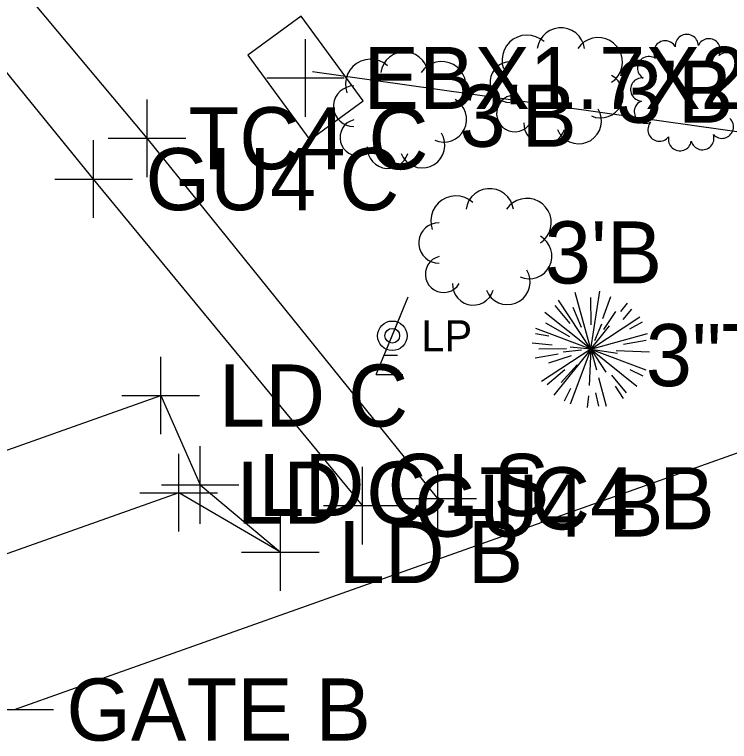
# Model space of a CAD drawing. Extents: x 1363693 to 1365209, y 422201 to 424153.
# Drawn here: x 1363860.29 to 1363878.71, y 423091.66 to 423110.38 of the extents above; entities that cross this region are included whole.
import ezdxf

# ---------------------------------------------------------------- set-up
doc = ezdxf.new("R2010")
doc.units = 0
for name, color, linetype in [('BASELINE-CL-RW', 7, 'Continuous'), ('PV_X_Driveway', 7, 'Continuous'), ('RD_X_Fence', 7, 'Continuous'), ('RD_X_Misc_Items', 7, 'Continuous'), ('RD_X_Text', 7, 'Continuous'), ('SG_X_Wiring', 7, 'Continuous'), ('SV_X_Original_Ground', 7, 'Continuous'), ('SV_X_Shot_Marker', 7, 'Continuous'), ('UT_X_Electric', 7, 'Continuous'), ('UT_X_Electric_Cells', 7, 'Continuous'), ('VG_X_Cells', 7, 'Continuous'), ('VG_X_Text', 7, 'Continuous')]:
    doc.layers.add(name, color=color, linetype=linetype)

msp = doc.modelspace()

# ---------------------------------------------------------------- linework, layer by layer
at = {"layer": 'BASELINE-CL-RW'}
msp.add_lwpolyline([(1363871.193, 423097.923), (1363863.7, 423107.198), (1363855.331, 423117.197), (1363852.206, 423120.83)], dxfattribs=at)
at = {"layer": 'PV_X_Driveway'}
msp.add_lwpolyline([(1363869.251, 423097.736), (1363862.325, 423106.145), (1363854.135, 423116.203), (1363852, 423118.789), (1363852.206, 423120.83)], dxfattribs=at)
at = {"layer": 'RD_X_Fence'}
msp.add_line((1363860.286, 423092.484), (1363885.607, 423101.471), dxfattribs=at)
at = {"layer": 'RD_X_Misc_Items'}
for p, q in [((1363869.608, 423101.11), (1363870.434, 423103.11)), ((1363869.815, 423101.61), (1363870.227, 423102.61)), ((1363869.815, 423101.61), (1363870.155, 423101.61)), ((1363869.608, 423101.11), (1363870.289, 423101.11))]:
    msp.add_line(p, q, dxfattribs=at)
for radius in [0.38, 0.19]:
    msp.add_circle((1363870.021, 423102.11), radius, dxfattribs=at)
at = {"layer": 'SG_X_Wiring'}
for p, q in [((1363850.877, 423095.89), (1363864.054, 423100.572)), ((1363864.054, 423100.572), (1363865.07, 423098.269)), ((1363865.07, 423098.269), (1363867.138, 423096.54)), ((1363864.519, 423098.068), (1363851.566, 423093.462)), ((1363867.138, 423096.54), (1363864.519, 423098.068))]:
    msp.add_line(p, q, dxfattribs=at)
at = {"layer": 'SV_X_Original_Ground'}
msp.add_line((1363859.286, 423092.484), (1363861.286, 423092.484), dxfattribs=at)
at = {"layer": 'SV_X_Shot_Marker'}
for p, q in [((1363867.784, 423107.75), (1363867.784, 423109.75)), ((1363866.784, 423108.75), (1363868.784, 423108.75)), ((1363863.7, 423106.198), (1363863.7, 423108.198)), ((1363862.325, 423105.145), (1363862.325, 423107.145)), ((1363862.7, 423107.198), (1363864.7, 423107.198)), ((1363861.325, 423106.145), (1363863.325, 423106.145)), ((1363864.054, 423099.572), (1363864.054, 423101.572)), ((1363863.054, 423100.572), (1363865.054, 423100.572)), ((1363865.07, 423097.269), (1363865.07, 423099.269)), ((1363864.519, 423097.068), (1363864.519, 423099.068)), ((1363871.193, 423096.923), (1363871.193, 423098.923)), ((1363869.251, 423096.736), (1363869.251, 423098.736)), ((1363864.07, 423098.269), (1363866.07, 423098.269)), ((1363863.519, 423098.068), (1363865.519, 423098.068)), ((1363870.193, 423097.923), (1363872.193, 423097.923)), ((1363868.251, 423097.736), (1363870.251, 423097.736)), ((1363867.138, 423095.54), (1363867.138, 423097.54)), ((1363866.138, 423096.54), (1363868.138, 423096.54))]:
    msp.add_line(p, q, dxfattribs=at)
at = {"layer": 'UT_X_Electric'}
msp.add_lwpolyline([(1363867.968, 423108.916), (1363973.038, 423094.077), (1364006.657, 423093.464)], dxfattribs=at)
at = {"layer": 'UT_X_Electric_Cells'}
msp.add_lwpolyline([(1363867.896, 423107.159), (1363869.268, 423108.164), (1363867.672, 423110.341), (1363866.3, 423109.336)], close=True, dxfattribs=at)
msp.add_lwpolyline([(1363867.896, 423107.159), (1363869.268, 423108.164), (1363867.672, 423110.341), (1363866.3, 423109.336)], close=True, dxfattribs=at)
at = {"layer": 'VG_X_Cells'}
for p, q in [((1363875.136, 423101.764), (1363874.735, 423103.227)), ((1363875.136, 423101.764), (1363875.367, 423103.263)), ((1363875.445, 423102.559), (1363875.651, 423103.119)), ((1363875.445, 423102.559), (1363875.651, 423103.119)), ((1363875.136, 423101.764), (1363874.303, 423103.031)), ((1363875.145, 423102.389), (1363875.139, 423103.1)), ((1363875.914, 423102.736), (1363876.084, 423102.948)), ((1363874.602, 423102.429), (1363874.22, 423102.887)), ((1363874.898, 423102.323), (1363874.679, 423102.839)), ((1363875.473, 423102.27), (1363875.784, 423102.736)), ((1363875.969, 423102.533), (1363876.195, 423102.798)), ((1363875.136, 423101.764), (1363873.952, 423102.712)), ((1363875.136, 423101.764), (1363876.403, 423102.597)), ((1363874.599, 423102.085), (1363873.981, 423102.434)), ((1363875.136, 423101.764), (1363875.617, 423102.365)), ((1363875.237, 423101.986), (1363875.425, 423102.414)), ((1363876.144, 423102.289), (1363876.467, 423102.468)), ((1363875.136, 423101.764), (1363873.717, 423102.299)), ((1363875.136, 423101.764), (1363876.599, 423102.165)), ((1363874.054, 423102.101), (1363873.712, 423102.164)), ((1363875.979, 423101.894), (1363876.567, 423101.996)), ((1363874.145, 423101.868), (1363873.628, 423101.923)), ((1363875.136, 423101.764), (1363874.607, 423101.82)), ((1363874.293, 423101.634), (1363873.705, 423101.532)), ((1363874.511, 423101.773), (1363873.8, 423101.767)), ((1363875.136, 423101.764), (1363873.869, 423100.931)), ((1363875.136, 423101.764), (1363874.188, 423100.58)), ((1363874.893, 423101.74), (1363874.428, 423101.689)), ((1363875.136, 423101.764), (1363874.601, 423100.345)), ((1363875.136, 423101.764), (1363875.092, 423100.832)), ((1363875.136, 423101.764), (1363875.283, 423101.229)), ((1363875.136, 423101.764), (1363875.524, 423101.175)), ((1363875.136, 423101.764), (1363876.32, 423100.816)), ((1363875.136, 423101.764), (1363876.555, 423101.229)), ((1363875.136, 423101.764), (1363875.822, 423101.66)), ((1363875.791, 423101.733), (1363876.651, 423101.693)), ((1363874.63, 423101.596), (1363874.049, 423101.403)), ((1363874.471, 423101.23), (1363874.013, 423100.848)), ((1363874.782, 423101.365), (1363874.375, 423100.908)), ((1363876.146, 423101.243), (1363876.478, 423101.082)), ((1363875.67, 423101.099), (1363876.052, 423100.641)), ((1363875.336, 423101.033), (1363875.537, 423100.301)), ((1363874.615, 423100.754), (1363874.454, 423100.422)), ((1363875.762, 423100.813), (1363875.969, 423100.497)), ((1363875.077, 423100.562), (1363875.044, 423100.263)), ((1363875.257, 423100.637), (1363875.334, 423100.298))]:
    msp.add_line(p, q, dxfattribs=at)
for points in [[(1363874.977, 423109.512), (1363874.95, 423109.626), (1363874.901, 423109.733), (1363874.833, 423109.828), (1363874.749, 423109.909), (1363874.65, 423109.972), (1363874.541, 423110.016), (1363874.426, 423110.038), (1363874.309, 423110.038), (1363874.194, 423110.016), (1363874.085, 423109.972), (1363873.987, 423109.909), (1363873.902, 423109.828), (1363873.834, 423109.733), (1363873.786, 423109.626), (1363873.758, 423109.512)], [(1363873.932, 423109.686), (1363873.834, 423109.76), (1363873.724, 423109.814), (1363873.606, 423109.846), (1363873.484, 423109.855), (1363873.362, 423109.841), (1363873.246, 423109.804), (1363873.138, 423109.746), (1363873.043, 423109.669), (1363872.964, 423109.575), (1363872.904, 423109.468), (1363872.866, 423109.352), (1363872.85, 423109.231), (1363872.857, 423109.108), (1363872.887, 423108.99)], [(1363875.674, 423108.642), (1363875.765, 423108.715), (1363875.84, 423108.804), (1363875.898, 423108.905), (1363875.936, 423109.016), (1363875.953, 423109.131), (1363875.948, 423109.248), (1363875.922, 423109.362), (1363875.875, 423109.468), (1363875.809, 423109.565), (1363875.726, 423109.647), (1363875.63, 423109.713), (1363875.523, 423109.76), (1363875.409, 423109.786), (1363875.293, 423109.791), (1363875.177, 423109.774), (1363875.067, 423109.736), (1363874.966, 423109.678), (1363874.877, 423109.603), (1363874.803, 423109.512)], [(1363870.942, 423108.892), (1363870.915, 423109.006), (1363870.866, 423109.113), (1363870.798, 423109.208), (1363870.714, 423109.289), (1363870.615, 423109.352), (1363870.506, 423109.396), (1363870.391, 423109.418), (1363870.274, 423109.418), (1363870.159, 423109.396), (1363870.05, 423109.352), (1363869.952, 423109.289), (1363869.867, 423109.208), (1363869.799, 423109.113), (1363869.751, 423109.006), (1363869.723, 423108.892)], [(1363869.897, 423109.066), (1363869.799, 423109.14), (1363869.689, 423109.194), (1363869.571, 423109.226), (1363869.449, 423109.235), (1363869.327, 423109.221), (1363869.211, 423109.184), (1363869.103, 423109.126), (1363869.008, 423109.049), (1363868.929, 423108.955), (1363868.869, 423108.848), (1363868.831, 423108.732), (1363868.815, 423108.611), (1363868.822, 423108.488), (1363868.852, 423108.37)], [(1363871.639, 423108.022), (1363871.73, 423108.095), (1363871.805, 423108.184), (1363871.863, 423108.285), (1363871.901, 423108.396), (1363871.918, 423108.511), (1363871.913, 423108.628), (1363871.887, 423108.742), (1363871.84, 423108.848), (1363871.774, 423108.945), (1363871.691, 423109.027), (1363871.595, 423109.093), (1363871.488, 423109.14), (1363871.374, 423109.166), (1363871.258, 423109.171), (1363871.142, 423109.154), (1363871.032, 423109.116), (1363870.931, 423109.058), (1363870.842, 423108.983), (1363870.768, 423108.892)], [(1363873.062, 423109.164), (1363872.965, 423109.155), (1363872.873, 423109.129), (1363872.786, 423109.086), (1363872.71, 423109.028), (1363872.645, 423108.956), (1363872.594, 423108.874), (1363872.559, 423108.784), (1363872.541, 423108.69), (1363872.541, 423108.593), (1363872.559, 423108.499), (1363872.594, 423108.409), (1363872.645, 423108.327), (1363872.71, 423108.255), (1363872.786, 423108.197), (1363872.873, 423108.154), (1363872.965, 423108.128), (1363873.062, 423108.119)], [(1363875.151, 423107.771), (1363875.257, 423107.736), (1363875.367, 423107.721), (1363875.478, 423107.728), (1363875.586, 423107.755), (1363875.686, 423107.803), (1363875.776, 423107.868), (1363875.852, 423107.95), (1363875.911, 423108.044), (1363875.951, 423108.148), (1363875.971, 423108.257), (1363875.969, 423108.368), (1363875.947, 423108.477), (1363875.904, 423108.58), (1363875.843, 423108.673), (1363875.765, 423108.752), (1363875.674, 423108.816)], [(1363869.027, 423108.544), (1363868.93, 423108.535), (1363868.838, 423108.509), (1363868.751, 423108.466), (1363868.675, 423108.408), (1363868.61, 423108.336), (1363868.559, 423108.254), (1363868.524, 423108.164), (1363868.506, 423108.07), (1363868.506, 423107.973), (1363868.524, 423107.879), (1363868.559, 423107.789), (1363868.61, 423107.707), (1363868.675, 423107.635), (1363868.751, 423107.577), (1363868.838, 423107.534), (1363868.93, 423107.508), (1363869.027, 423107.499)], [(1363871.116, 423107.151), (1363871.222, 423107.116), (1363871.332, 423107.101), (1363871.443, 423107.108), (1363871.551, 423107.135), (1363871.651, 423107.183), (1363871.741, 423107.248), (1363871.817, 423107.33), (1363871.876, 423107.424), (1363871.916, 423107.528), (1363871.936, 423107.637), (1363871.934, 423107.748), (1363871.912, 423107.857), (1363871.869, 423107.96), (1363871.808, 423108.053), (1363871.73, 423108.132), (1363871.639, 423108.196)], [(1363873.062, 423108.293), (1363872.975, 423108.261), (1363872.896, 423108.214), (1363872.828, 423108.151), (1363872.774, 423108.077), (1363872.735, 423107.993), (1363872.713, 423107.904), (1363872.709, 423107.811), (1363872.723, 423107.72), (1363872.755, 423107.634), (1363872.803, 423107.555), (1363872.865, 423107.487), (1363872.939, 423107.432), (1363873.023, 423107.393), (1363873.112, 423107.371), (1363873.204, 423107.367), (1363873.296, 423107.381), (1363873.382, 423107.412), (1363873.461, 423107.46), (1363873.529, 423107.522), (1363873.584, 423107.597)], [(1363874.281, 423107.422), (1363874.333, 423107.321), (1363874.404, 423107.232), (1363874.491, 423107.158), (1363874.59, 423107.103), (1363874.698, 423107.068), (1363874.812, 423107.054), (1363874.925, 423107.063), (1363875.035, 423107.093), (1363875.137, 423107.144), (1363875.227, 423107.213), (1363875.302, 423107.299), (1363875.359, 423107.398), (1363875.395, 423107.506), (1363875.411, 423107.618), (1363875.404, 423107.732), (1363875.375, 423107.842), (1363875.326, 423107.945)], [(1363869.027, 423107.673), (1363868.94, 423107.641), (1363868.861, 423107.594), (1363868.793, 423107.531), (1363868.739, 423107.457), (1363868.7, 423107.373), (1363868.678, 423107.284), (1363868.674, 423107.191), (1363868.688, 423107.1), (1363868.72, 423107.014), (1363868.768, 423106.935), (1363868.83, 423106.867), (1363868.904, 423106.812), (1363868.988, 423106.773), (1363869.077, 423106.751), (1363869.169, 423106.747), (1363869.261, 423106.761), (1363869.347, 423106.792), (1363869.426, 423106.84), (1363869.494, 423106.902), (1363869.549, 423106.977)], [(1363873.41, 423107.597), (1363873.416, 423107.494), (1363873.441, 423107.394), (1363873.485, 423107.301), (1363873.546, 423107.219), (1363873.621, 423107.149), (1363873.709, 423107.095), (1363873.805, 423107.059), (1363873.907, 423107.042), (1363874.009, 423107.045), (1363874.11, 423107.068), (1363874.204, 423107.109), (1363874.288, 423107.167), (1363874.36, 423107.241), (1363874.416, 423107.327), (1363874.455, 423107.422)], [(1363870.246, 423106.802), (1363870.298, 423106.701), (1363870.369, 423106.612), (1363870.456, 423106.538), (1363870.555, 423106.483), (1363870.663, 423106.448), (1363870.777, 423106.434), (1363870.89, 423106.443), (1363871, 423106.473), (1363871.102, 423106.524), (1363871.192, 423106.593), (1363871.267, 423106.679), (1363871.324, 423106.778), (1363871.36, 423106.886), (1363871.376, 423106.998), (1363871.369, 423107.112), (1363871.34, 423107.222), (1363871.291, 423107.325)], [(1363869.375, 423106.977), (1363869.381, 423106.874), (1363869.406, 423106.774), (1363869.45, 423106.681), (1363869.511, 423106.599), (1363869.586, 423106.529), (1363869.674, 423106.475), (1363869.77, 423106.439), (1363869.872, 423106.422), (1363869.974, 423106.425), (1363870.075, 423106.448), (1363870.169, 423106.489), (1363870.253, 423106.547), (1363870.325, 423106.621), (1363870.381, 423106.707), (1363870.42, 423106.802)], [(1363873.141, 423105.371), (1363873.114, 423105.485), (1363873.065, 423105.592), (1363872.997, 423105.687), (1363872.913, 423105.768), (1363872.814, 423105.831), (1363872.705, 423105.875), (1363872.59, 423105.897), (1363872.473, 423105.897), (1363872.358, 423105.875), (1363872.249, 423105.831), (1363872.151, 423105.768), (1363872.066, 423105.687), (1363871.998, 423105.592), (1363871.95, 423105.485), (1363871.922, 423105.371)], [(1363872.096, 423105.545), (1363871.998, 423105.619), (1363871.888, 423105.673), (1363871.77, 423105.705), (1363871.648, 423105.714), (1363871.526, 423105.7), (1363871.41, 423105.663), (1363871.302, 423105.605), (1363871.207, 423105.528), (1363871.128, 423105.434), (1363871.068, 423105.327), (1363871.03, 423105.211), (1363871.014, 423105.09), (1363871.021, 423104.967), (1363871.051, 423104.849)], [(1363873.838, 423104.501), (1363873.929, 423104.574), (1363874.004, 423104.663), (1363874.062, 423104.764), (1363874.1, 423104.875), (1363874.117, 423104.99), (1363874.112, 423105.107), (1363874.086, 423105.221), (1363874.039, 423105.327), (1363873.973, 423105.424), (1363873.89, 423105.506), (1363873.794, 423105.572), (1363873.687, 423105.619), (1363873.573, 423105.645), (1363873.457, 423105.65), (1363873.341, 423105.633), (1363873.231, 423105.595), (1363873.13, 423105.537), (1363873.041, 423105.462), (1363872.967, 423105.371)], [(1363871.226, 423105.023), (1363871.129, 423105.014), (1363871.037, 423104.988), (1363870.95, 423104.945), (1363870.874, 423104.887), (1363870.809, 423104.815), (1363870.758, 423104.733), (1363870.723, 423104.643), (1363870.705, 423104.549), (1363870.705, 423104.452), (1363870.723, 423104.358), (1363870.758, 423104.268), (1363870.809, 423104.186), (1363870.874, 423104.114), (1363870.95, 423104.056), (1363871.037, 423104.013), (1363871.129, 423103.987), (1363871.226, 423103.978)], [(1363873.315, 423103.63), (1363873.421, 423103.595), (1363873.531, 423103.58), (1363873.642, 423103.587), (1363873.75, 423103.614), (1363873.85, 423103.662), (1363873.94, 423103.727), (1363874.016, 423103.809), (1363874.075, 423103.903), (1363874.115, 423104.007), (1363874.135, 423104.116), (1363874.133, 423104.227), (1363874.111, 423104.336), (1363874.068, 423104.439), (1363874.007, 423104.532), (1363873.929, 423104.611), (1363873.838, 423104.675)], [(1363871.226, 423104.152), (1363871.139, 423104.12), (1363871.06, 423104.073), (1363870.992, 423104.01), (1363870.938, 423103.936), (1363870.899, 423103.852), (1363870.877, 423103.763), (1363870.873, 423103.67), (1363870.887, 423103.579), (1363870.919, 423103.493), (1363870.967, 423103.414), (1363871.029, 423103.346), (1363871.103, 423103.291), (1363871.187, 423103.252), (1363871.276, 423103.23), (1363871.368, 423103.226), (1363871.46, 423103.24), (1363871.546, 423103.271), (1363871.625, 423103.319), (1363871.693, 423103.381), (1363871.748, 423103.456)], [(1363872.445, 423103.281), (1363872.497, 423103.18), (1363872.568, 423103.091), (1363872.655, 423103.017), (1363872.754, 423102.962), (1363872.862, 423102.927), (1363872.976, 423102.913), (1363873.089, 423102.922), (1363873.199, 423102.952), (1363873.301, 423103.003), (1363873.391, 423103.072), (1363873.466, 423103.158), (1363873.523, 423103.257), (1363873.559, 423103.365), (1363873.575, 423103.477), (1363873.568, 423103.591), (1363873.539, 423103.701), (1363873.49, 423103.804)], [(1363871.574, 423103.456), (1363871.58, 423103.353), (1363871.605, 423103.253), (1363871.649, 423103.16), (1363871.71, 423103.078), (1363871.785, 423103.008), (1363871.873, 423102.954), (1363871.969, 423102.918), (1363872.071, 423102.901), (1363872.173, 423102.904), (1363872.274, 423102.927), (1363872.368, 423102.968), (1363872.452, 423103.026), (1363872.524, 423103.1), (1363872.58, 423103.186), (1363872.619, 423103.281)]]:
    msp.add_lwpolyline(points, dxfattribs=at)
for points in [[(1363877.579, 423108.415), (1363877.668, 423108.363), (1363877.668, 423108.363), (1363877.565, 423108.363)], [(1363877.565, 423108.363), (1363877.668, 423108.363), (1363877.668, 423108.363), (1363877.579, 423108.311)], [(1363877.616, 423108.452), (1363877.668, 423108.363), (1363877.668, 423108.363), (1363877.579, 423108.415)], [(1363877.579, 423108.311), (1363877.668, 423108.363), (1363877.668, 423108.363), (1363877.616, 423108.274)], [(1363877.668, 423108.466), (1363877.668, 423108.363), (1363877.668, 423108.363), (1363877.616, 423108.452)], [(1363877.616, 423108.274), (1363877.668, 423108.363), (1363877.668, 423108.363), (1363877.668, 423108.26)], [(1363877.72, 423108.452), (1363877.668, 423108.363), (1363877.668, 423108.363), (1363877.668, 423108.466)], [(1363877.757, 423108.415), (1363877.668, 423108.363), (1363877.668, 423108.363), (1363877.72, 423108.452)], [(1363877.771, 423108.363), (1363877.668, 423108.363), (1363877.668, 423108.363), (1363877.757, 423108.415)], [(1363877.668, 423108.26), (1363877.668, 423108.363), (1363877.668, 423108.363), (1363877.72, 423108.274)], [(1363877.72, 423108.274), (1363877.668, 423108.363), (1363877.668, 423108.363), (1363877.757, 423108.311)], [(1363877.757, 423108.311), (1363877.668, 423108.363), (1363877.668, 423108.363), (1363877.771, 423108.363)]]:
    msp.add_lwpolyline(points, close=True, dxfattribs=at)
for centre, start, end in [((1363877.611, 423109.576), 1.241, 184.1237), ((1363877.054, 423109.411), 28.9333, 211.816), ((1363878.181, 423109.464), 333.5487, 156.4314), ((1363876.637, 423109.005), 56.6256, 239.5083), ((1363878.634, 423109.099), 305.8564, 128.7391), ((1363876.457, 423108.453), 84.3179, 267.2006), ((1363876.554, 423107.88), 112.0103, 294.8929), ((1363876.906, 423107.417), 139.7026, 322.5852), ((1363878.515, 423107.493), 222.7795, 45.6622), ((1363877.433, 423107.171), 167.3949, 350.2776), ((1363878.014, 423107.199), 195.0872, 17.9699)]:
    msp.add_arc(centre, 0.298, start, end, dxfattribs=at)

# ---------------------------------------------------------------- texts
at = {"layer": 'RD_X_Text'}
msp.add_text('LP', height=0.8, dxfattribs=at).set_placement((1363870.771, 423101.71))
at = {"layer": 'SV_X_Original_Ground'}
msp.add_text('GATE B', height=1.6, dxfattribs=at).set_placement((1363861.623, 423091.684))
at = {"layer": 'SV_X_Shot_Marker'}
for s, p in [('EBX1.7X2.7', (1363869.284, 423107.95)), ('TC4 C', (1363864.771, 423106.398)), ('GU4 C', (1363863.662, 423105.345)), ('LD C', (1363865.554, 423099.772)), ('LD CLS', (1363866.57, 423097.469)), ('LD C', (1363866.019, 423097.268)), ('TC4 B', (1363872.264, 423097.123)), ('GU4 B', (1363870.588, 423096.936)), ('LD B', (1363868.638, 423095.74))]:
    msp.add_text(s, height=1.6, dxfattribs=at).set_placement(p)
at = {"layer": 'VG_X_Text'}
for s, p in [("3'B", (1363875.785, 423107.598)), ("3'B", (1363871.75, 423106.978)), ("3'B", (1363873.949, 423103.457)), ('3"T', (1363876.554, 423100.812))]:
    msp.add_text(s, height=1.6, dxfattribs=at).set_placement(p)

doc.saveas('drawing.dxf')
